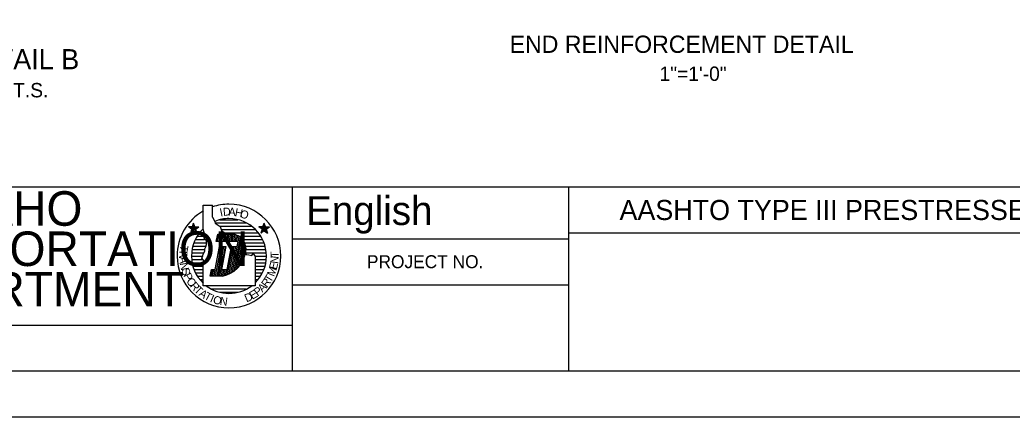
# Model space of a CAD drawing. Extents: x 0 to 45.3, y 0 to 31.4.
# Drawn here: x 21.72 to 36.08, y 0 to 5.75 of the extents above; entities that cross this region are included whole.
import ezdxf

# ---------------------------------------------------------------- set-up
doc = ezdxf.new("R2010")
doc.units = 0
for name, color, linetype in [('BORDER_ANNO_Cutsheet', 7, 'Continuous'), ('BRDG_ANNO_Anno-Sheet', 7, 'Continuous'), ('BRDG_ANNO_General-Notes', 7, 'Continuous')]:
    doc.layers.add(name, color=color, linetype=linetype)

msp = doc.modelspace()

# ---------------------------------------------------------------- linework, layer by layer
at = {"layer": 'BORDER_ANNO_Cutsheet'}
msp.add_lwpolyline([(0, 29.333), (45.333, 29.333), (45.333, 0), (0, 0)], close=True, dxfattribs=at)
at = {"layer": 'BRDG_ANNO_Anno-Sheet'}
for p, q in [((2, 3.333), (25.667, 3.333)), ((25.667, 0.667), (25.667, 3.333)), ((25.667, 3.333), (44.667, 3.333)), ((29.667, 0.667), (29.667, 3.333)), ((24.379, 2.723), (24.379, 3.071)), ((24.379, 3.071), (24.511, 3.071)), ((24.511, 2.897), (24.511, 3.071)), ((24.511, 2.897), (24.546, 2.835)), ((24.268, 2.72), (24.163, 2.754)), ((24.221, 2.754), (24.163, 2.754)), ((24.21, 2.72), (24.163, 2.754)), ((24.258, 2.754), (24.192, 2.664)), ((24.21, 2.72), (24.316, 2.754)), ((24.221, 2.754), (24.239, 2.809)), ((24.221, 2.754), (24.287, 2.664)), ((24.239, 2.698), (24.239, 2.809)), ((24.258, 2.754), (24.239, 2.809)), ((24.258, 2.754), (24.316, 2.754)), ((24.268, 2.72), (24.316, 2.754)), ((24.546, 2.835), (24.552, 2.807)), ((24.552, 2.807), (24.622, 2.758)), ((24.556, 2.811), (25.001, 2.811)), ((24.62, 2.859), (24.877, 2.859)), ((24.62, 2.763), (25.076, 2.763)), ((24.622, 2.758), (24.643, 2.703)), ((25.29, 2.72), (25.184, 2.754)), ((25.232, 2.72), (25.184, 2.754)), ((25.242, 2.754), (25.184, 2.754)), ((25.279, 2.754), (25.213, 2.664)), ((25.232, 2.72), (25.337, 2.754)), ((25.242, 2.754), (25.261, 2.809)), ((25.242, 2.754), (25.308, 2.664)), ((25.261, 2.698), (25.261, 2.809)), ((25.279, 2.754), (25.261, 2.809)), ((25.279, 2.754), (25.337, 2.754)), ((25.29, 2.72), (25.337, 2.754)), ((24.21, 2.72), (24.192, 2.664)), ((24.239, 2.698), (24.192, 2.664)), ((24.239, 2.698), (24.287, 2.664)), ((24.268, 2.72), (24.287, 2.664)), ((24.289, 2.619), (24.39, 2.619)), ((24.322, 2.667), (24.392, 2.667)), ((24.366, 2.715), (24.382, 2.715)), ((24.392, 2.675), (24.379, 2.723)), ((24.392, 2.633), (24.392, 2.675)), ((24.392, 2.598), (24.392, 2.633)), ((24.4, 2.571), (24.392, 2.598)), ((24.567, 2.542), (24.587, 2.647)), ((24.586, 2.542), (24.605, 2.647)), ((24.587, 2.647), (24.817, 2.647)), ((24.607, 2.542), (24.627, 2.647)), ((24.628, 2.542), (24.648, 2.647)), ((24.638, 2.715), (25.134, 2.715)), ((24.643, 2.703), (24.712, 2.647)), ((24.649, 2.542), (24.669, 2.647)), ((24.67, 2.542), (24.69, 2.647)), ((24.688, 2.667), (25.177, 2.667)), ((24.692, 2.542), (24.711, 2.647)), ((24.712, 2.542), (24.732, 2.647)), ((24.734, 2.542), (24.753, 2.647)), ((24.755, 2.542), (24.775, 2.647)), ((24.777, 2.542), (24.796, 2.647)), ((24.797, 2.542), (24.817, 2.647)), ((24.799, 2.099), (24.896, 2.616)), ((24.818, 2.542), (24.837, 2.642)), ((24.823, 2.114), (24.915, 2.603)), ((24.84, 2.542), (24.857, 2.636)), ((24.848, 2.134), (24.932, 2.585)), ((24.861, 2.542), (24.877, 2.627)), ((24.892, 2.619), (25.21, 2.619)), ((25.232, 2.72), (25.213, 2.664)), ((25.261, 2.698), (25.213, 2.664)), ((25.261, 2.698), (25.308, 2.664)), ((25.29, 2.72), (25.308, 2.664)), ((29.667, 2.667), (40.333, 2.667)), ((24.227, 2.475), (24.415, 2.475)), ((24.242, 2.523), (24.425, 2.523)), ((24.262, 2.571), (24.398, 2.571)), ((24.427, 2.557), (24.4, 2.571)), ((24.4, 2.438), (24.413, 2.467)), ((24.413, 2.467), (24.427, 2.501)), ((24.427, 2.522), (24.427, 2.557)), ((24.427, 2.501), (24.427, 2.522)), ((24.552, 2.14), (24.615, 2.473)), ((24.555, 2.042), (24.636, 2.473)), ((24.882, 2.542), (24.567, 2.542)), ((24.577, 2.042), (24.657, 2.473)), ((24.598, 2.042), (24.678, 2.473)), ((24.615, 2.473), (24.707, 2.473)), ((24.619, 2.042), (24.7, 2.473)), ((24.707, 2.473), (24.644, 2.14)), ((24.725, 2.14), (24.787, 2.473)), ((24.729, 2.063), (24.806, 2.473)), ((24.752, 2.073), (24.827, 2.473)), ((24.775, 2.084), (24.848, 2.473)), ((24.787, 2.473), (24.869, 2.473)), ((24.869, 2.473), (24.882, 2.542)), ((24.874, 2.158), (24.95, 2.566)), ((24.901, 2.187), (24.967, 2.542)), ((24.929, 2.225), (24.982, 2.509)), ((24.947, 2.571), (25.237, 2.571)), ((24.962, 2.29), (24.994, 2.46)), ((24.977, 2.523), (25.258, 2.523)), ((24.992, 2.475), (25.273, 2.475)), ((25.667, 2.583), (29.667, 2.583)), ((24.208, 2.331), (24.37, 2.331)), ((24.21, 2.379), (24.387, 2.379)), ((24.217, 2.427), (24.398, 2.427)), ((24.358, 2.3), (24.372, 2.334)), ((24.379, 2.279), (24.358, 2.3)), ((24.372, 2.334), (24.379, 2.362)), ((24.379, 2.362), (24.4, 2.404)), ((24.4, 2.404), (24.4, 2.438)), ((24.988, 2.37), (24.997, 2.355)), ((24.99, 2.379), (25.29, 2.379)), ((24.997, 2.427), (25.283, 2.427)), ((24.997, 2.355), (25.039, 2.348)), ((25.039, 2.348), (25.081, 2.342)), ((25.081, 2.342), (25.102, 2.369)), ((25.102, 2.369), (25.129, 2.328)), ((25.127, 2.331), (25.292, 2.331)), ((25.129, 2.328), (25.129, 1.903)), ((24.211, 2.283), (24.375, 2.283)), ((24.217, 2.235), (24.398, 2.235)), ((24.228, 2.188), (24.378, 2.188)), ((24.392, 2.258), (24.379, 2.279)), ((24.379, 2.203), (24.4, 2.223)), ((24.379, 1.903), (24.379, 2.203)), ((24.4, 2.244), (24.392, 2.258)), ((24.4, 2.223), (24.4, 2.244)), ((25.129, 2.235), (25.282, 2.235)), ((25.129, 2.188), (25.272, 2.188)), ((25.13, 2.283), (25.289, 2.283)), ((24.245, 2.139), (24.377, 2.139)), ((24.266, 2.091), (24.377, 2.091)), ((24.293, 2.043), (24.377, 2.043)), ((24.479, 2.042), (24.497, 2.14)), ((24.657, 2.042), (24.479, 2.042)), ((24.492, 2.042), (24.51, 2.14)), ((24.497, 2.14), (24.552, 2.14)), ((24.513, 2.042), (24.532, 2.14)), ((24.534, 2.042), (24.552, 2.14)), ((24.64, 2.042), (24.658, 2.14)), ((24.644, 2.14), (24.725, 2.14)), ((24.662, 2.043), (24.68, 2.14)), ((24.684, 2.049), (24.701, 2.14)), ((24.707, 2.056), (24.722, 2.14)), ((25.129, 2.139), (25.255, 2.139)), ((25.129, 2.091), (25.233, 2.091)), ((25.129, 2.043), (25.207, 2.043)), ((24.328, 1.995), (24.377, 1.995)), ((24.37, 1.948), (24.378, 1.948)), ((25.129, 1.903), (24.379, 1.903)), ((25.129, 1.995), (25.173, 1.995)), ((25.667, 1.917), (29.667, 1.917)), ((25.001, 1.855), (24.496, 1.855)), ((24.878, 1.807), (24.623, 1.807)), ((18.667, 1.333), (25.667, 1.333))]:
    msp.add_line(p, q, dxfattribs=at)
msp.add_lwpolyline([(2, 28.667), (44.667, 28.667), (44.667, 0.667), (2, 0.667)], close=True, dxfattribs=at)
for centre, radius, start, end in [((24.75, 2.333), 0.75, 90, 108.596), ((24.75, 2.333), 0.75, 0, 90), ((24.75, 2.333), 0.75, 119.6331, 180), ((24.75, 2.333), 0.542, 90, 112.1452), ((24.75, 2.333), 0.542, 0, 90), ((24.75, 2.333), 0.542, 133.1926, 180), ((24.778, 2.432), 0.219, 343.4981, 79.7362), ((24.75, 2.333), 0.75, 180, 270), ((24.75, 2.333), 0.542, 180.2644, 226.7946), ((24.58, 2.451), 0.416, 280.6479, 348.7719), ((24.75, 2.333), 0.75, 270, 0), ((24.75, 2.333), 0.542, 314.427, 0), ((24.75, 2.333), 0.542, 232.5658, 270), ((24.75, 2.333), 0.542, 270, 307.4536)]:
    msp.add_arc(centre, radius, start, end, dxfattribs=at)

# ---------------------------------------------------------------- texts
for s, height, p in [('IDAHO', 0.5, (20.512, 2.771)), ('English', 0.4167, (25.867, 2.782)), ('AASHTO TYPE III PRESTRESSED GIRDER', 0.29084, (30.401, 2.854)), ('TRANSPORTATION', 0.5, (18.863, 2.188)), ('PROJECT NO.', 0.1875, (26.746, 2.157)), ('DEPARTMENT', 0.5, (19.492, 1.604))]:
    msp.add_text(s, height=height, dxfattribs=at).set_placement(p)
for s, rotation, p in [('I', 11.9519, (24.629, 2.904)), ('D', 5.2118, (24.668, 2.913)), ('A', 357.8718, (24.742, 2.917)), ('H', 349.6318, (24.829, 2.912)), ('O', 342.1917, (24.899, 2.897)), ('T', 259.4265, (24.051, 2.501)), ('R', 266.0275, (24.035, 2.41)), ('A', 273.764, (24.031, 2.321)), ('N', 83.1932, (25.46, 2.217)), ('T', 90.4926, (25.469, 2.306)), ('N', 280.3758, (24.038, 2.228)), ('S', 287.9279, (24.057, 2.138)), ('M', 67.7139, (25.401, 2.027)), ('E', 75.6105, (25.439, 2.129)), ('P', 295.4976, (24.087, 2.054)), ('O', 302.6446, (24.127, 1.973)), ('T', 59.0362, (25.352, 1.94)), ('R', 309.9079, (24.178, 1.897)), ('T', 317.1211, (24.237, 1.828)), ('P', 37.6656, (25.164, 1.746)), ('A', 45, (25.234, 1.801)), ('R', 52.3344, (25.298, 1.868)), ('A', 324.6375, (24.304, 1.767)), ('T', 331.7503, (24.379, 1.716)), ('I', 337.0213, (24.466, 1.672)), ('O', 343.3287, (24.51, 1.654)), ('N', 351.6598, (24.612, 1.627)), ('D', 22.9887, (25.004, 1.661)), ('E', 30.5476, (25.087, 1.698))]:
    msp.add_text(s, height=0.116, rotation=rotation, dxfattribs=at).set_placement(p)
at = {"layer": 'BRDG_ANNO_General-Notes'}
for s, height, p in [('END REINFORCEMENT DETAIL', 0.25, (28.811, 5.274)), ('DETAIL B', 0.2917, (20.849, 5.036)), ('1"=1\'-0"', 0.2083, (30.98, 4.868)), ('N.T.S.', 0.2083, (21.348, 4.63))]:
    msp.add_text(s, height=height, dxfattribs=at).set_placement(p)

doc.saveas('drawing.dxf')
